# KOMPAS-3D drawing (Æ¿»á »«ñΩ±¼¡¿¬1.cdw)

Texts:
  Стандартные изделия
  Гайка  М10-6H.04 ГОСТ 5915-70
  Шайба C.10.31 ГОСТ 11371-78
  Болт М8-6gx32.36 ГОСТ 7796-70
  Гайка  М8-6H.04 ГОСТ 5915-70
  Шайба C.8.31 ГОСТ 11371-78
Dimensions and other numbers on the sheet: 7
